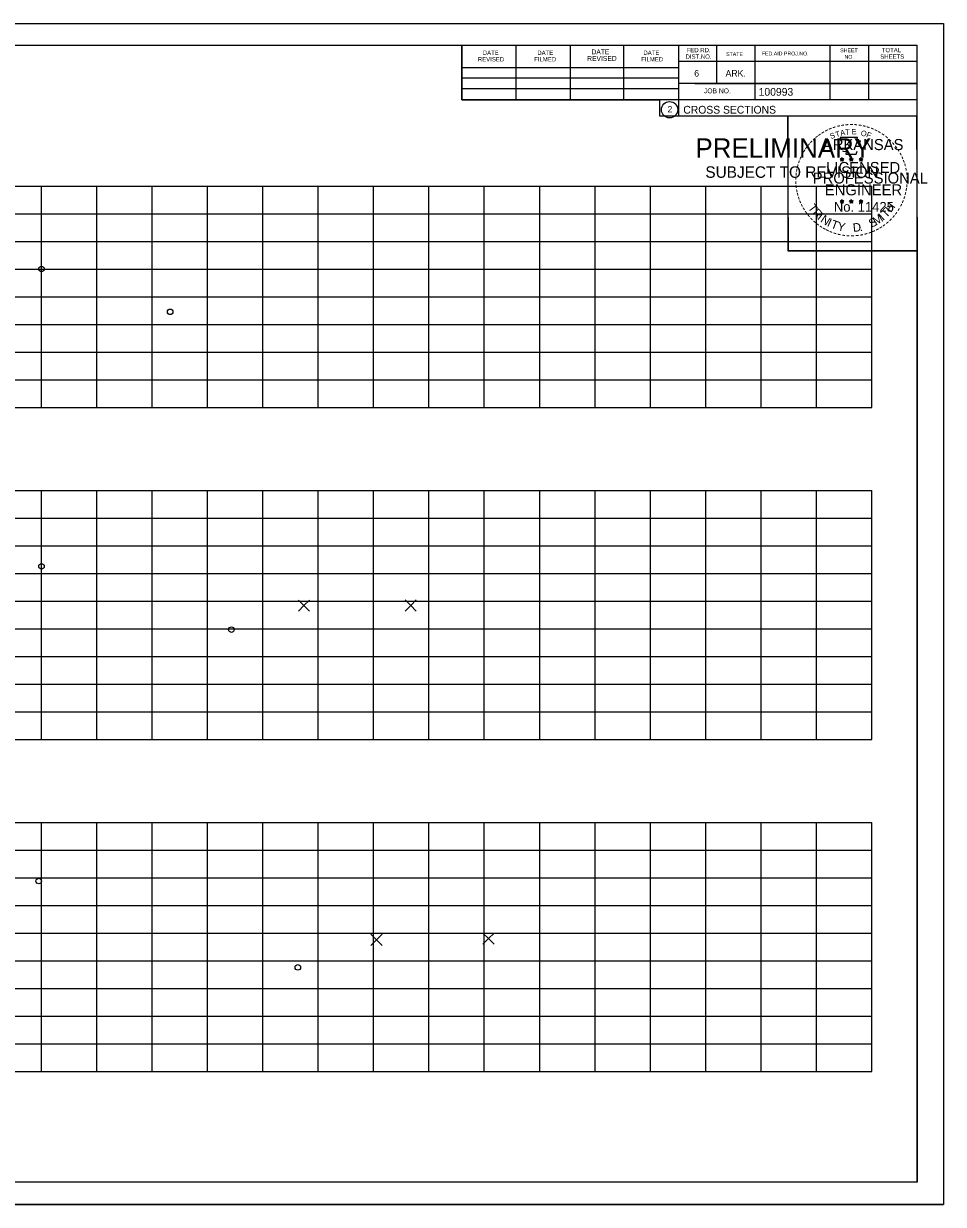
# Model space of a CAD drawing. Extents: x 4667 to 1632277, y -2100 to 724501.
# Drawn here: x 6136.3 to 6302.5, y -683.7 to -470.4 of the extents above; entities that cross this region are included whole.
import ezdxf

# ---------------------------------------------------------------- set-up
doc = ezdxf.new("R2010")
doc.units = 0
doc.layers.add('R_Grid', color=7, linetype='Continuous')
doc.layers.add('R_No Plot', color=7, linetype='Continuous')

msp = doc.modelspace()

# ---------------------------------------------------------------- linework, layer by layer
at = {"layer": 'R_Grid'}
for p, q in [((5989.52, -499.75), (6289.52, -499.75)), ((6139.52, -539.75), (6139.52, -499.75)), ((6149.52, -539.75), (6149.52, -499.75)), ((6159.52, -539.75), (6159.52, -499.75)), ((6169.52, -539.75), (6169.52, -499.75)), ((6179.52, -539.75), (6179.52, -499.75)), ((6189.52, -539.75), (6189.52, -499.75)), ((6199.52, -539.75), (6199.52, -499.75)), ((6209.52, -539.75), (6209.52, -499.75)), ((6219.52, -539.75), (6219.52, -499.75)), ((6229.52, -539.75), (6229.52, -499.75)), ((6239.52, -539.75), (6239.52, -499.75)), ((6249.52, -539.75), (6249.52, -499.75)), ((6259.52, -539.75), (6259.52, -499.75)), ((6269.52, -539.75), (6269.52, -499.75)), ((6279.52, -539.75), (6279.52, -499.75)), ((6289.52, -539.75), (6289.52, -499.75)), ((5989.52, -504.75), (6289.52, -504.75)), ((5989.52, -509.75), (6289.52, -509.75)), ((5989.52, -514.75), (6289.52, -514.75)), ((5989.52, -519.75), (6289.52, -519.75)), ((5989.52, -524.75), (6289.52, -524.75)), ((5989.52, -529.75), (6289.52, -529.75)), ((5989.52, -534.75), (6289.52, -534.75)), ((5989.52, -539.75), (6289.52, -539.75)), ((5989.52, -554.75), (6289.52, -554.75)), ((6139.52, -599.75), (6139.52, -554.75)), ((6149.52, -599.75), (6149.52, -554.75)), ((6159.52, -599.75), (6159.52, -554.75)), ((6169.52, -599.75), (6169.52, -554.75)), ((6179.52, -599.75), (6179.52, -554.75)), ((6189.52, -599.75), (6189.52, -554.75)), ((6199.52, -599.75), (6199.52, -554.75)), ((6209.52, -599.75), (6209.52, -554.75)), ((6219.52, -599.75), (6219.52, -554.75)), ((6229.52, -599.75), (6229.52, -554.75)), ((6239.52, -599.75), (6239.52, -554.75)), ((6249.52, -599.75), (6249.52, -554.75)), ((6259.52, -599.75), (6259.52, -554.75)), ((6269.52, -599.75), (6269.52, -554.75)), ((6279.52, -599.75), (6279.52, -554.75)), ((6289.52, -599.75), (6289.52, -554.75)), ((5989.52, -559.75), (6289.52, -559.75)), ((5989.52, -564.75), (6289.52, -564.75)), ((5989.52, -569.75), (6289.52, -569.75)), ((5989.52, -574.75), (6289.52, -574.75)), ((5989.52, -579.75), (6289.52, -579.75)), ((5989.52, -584.75), (6289.52, -584.75)), ((5989.52, -589.75), (6289.52, -589.75)), ((5989.52, -594.75), (6289.52, -594.75)), ((5989.52, -599.75), (6289.52, -599.75)), ((5989.52, -614.75), (6289.52, -614.75)), ((6139.52, -659.75), (6139.52, -614.75)), ((6149.52, -659.75), (6149.52, -614.75)), ((6159.52, -659.75), (6159.52, -614.75)), ((6169.52, -659.75), (6169.52, -614.75)), ((6179.52, -659.75), (6179.52, -614.75)), ((6189.52, -659.75), (6189.52, -614.75)), ((6199.52, -659.75), (6199.52, -614.75)), ((6209.52, -659.75), (6209.52, -614.75)), ((6219.52, -659.75), (6219.52, -614.75)), ((6229.52, -659.75), (6229.52, -614.75)), ((6239.52, -659.75), (6239.52, -614.75)), ((6249.52, -659.75), (6249.52, -614.75)), ((6259.52, -659.75), (6259.52, -614.75)), ((6269.52, -659.75), (6269.52, -614.75)), ((6279.52, -659.75), (6279.52, -614.75)), ((6289.52, -659.75), (6289.52, -614.75)), ((5989.52, -619.75), (6289.52, -619.75)), ((5989.52, -624.75), (6289.52, -624.75)), ((5989.52, -629.75), (6289.52, -629.75)), ((5989.52, -634.75), (6289.52, -634.75)), ((5989.52, -639.75), (6289.52, -639.75)), ((5989.52, -644.75), (6289.52, -644.75)), ((5989.52, -649.75), (6289.52, -649.75)), ((5989.52, -654.75), (6289.52, -654.75)), ((5989.52, -659.75), (6289.52, -659.75))]:
    msp.add_line(p, q, dxfattribs=at)
at = {"layer": 'R_No Plot'}
for p, q in [((5969.12, -470.4), (6302.46, -470.4)), ((5981.52, -474.29), (6297.7, -474.29)), ((6215.44, -484.17), (6215.44, -474.29)), ((6225.3, -484.17), (6225.3, -474.49)), ((6235.06, -484.17), (6235.06, -474.49)), ((6244.74, -484.17), (6244.74, -474.49)), ((6254.6, -474.29), (6254.6, -487.09)), ((6261.44, -474.29), (6261.44, -481.23)), ((6268.38, -474.29), (6268.38, -484.17)), ((6281.96, -474.29), (6281.96, -484.17)), ((6288.9, -474.29), (6288.9, -484.17)), ((6297.7, -679.75), (6297.7, -474.29)), ((6297.7, -477.23), (6254.6, -477.23)), ((6297.7, -477.21), (6297.7, -477.21)), ((6215.44, -478.31), (6254.6, -478.31)), ((6215.44, -480.17), (6254.6, -480.17)), ((6215.44, -484.17), (6215.44, -482.11)), ((6215.44, -482.11), (6254.6, -482.11)), ((6297.7, -481.23), (6254.6, -481.23)), ((6257.56, -481.23), (6297.7, -481.23)), ((6297.7, -484.17), (6215.44, -484.17)), ((6254.6, -487.09), (6297.7, -487.09)), ((6283.79, -494.84), (6284.14, -494.95)), ((6283.79, -494.84), (6284.04, -494.88)), ((6283.79, -494.84), (6284.03, -494.96)), ((6284.14, -494.59), (6284.1, -494.84)), ((6284.14, -494.95), (6284.14, -494.59)), ((6284.14, -494.59), (6284.19, -494.84)), ((6284.49, -494.84), (6284.14, -494.95)), ((6284.49, -494.84), (6284.2, -494.89)), ((6284.49, -494.84), (6284.28, -494.94)), ((6285.46, -494.84), (6285.81, -494.95)), ((6285.46, -494.84), (6285.71, -494.88)), ((6285.46, -494.84), (6285.7, -494.96)), ((6285.81, -494.59), (6285.77, -494.84)), ((6285.81, -494.95), (6285.81, -494.59)), ((6285.81, -494.59), (6285.86, -494.84)), ((6286.16, -494.84), (6285.81, -494.95)), ((6286.16, -494.84), (6285.87, -494.89)), ((6286.16, -494.84), (6285.95, -494.94)), ((6287.22, -494.85), (6287.57, -494.96)), ((6287.22, -494.85), (6287.48, -494.9)), ((6287.22, -494.85), (6287.46, -494.97)), ((6287.57, -494.6), (6287.53, -494.85)), ((6287.57, -494.96), (6287.57, -494.6)), ((6287.57, -494.6), (6287.62, -494.85)), ((6287.92, -494.85), (6287.57, -494.96)), ((6287.92, -494.85), (6287.63, -494.9)), ((6287.92, -494.85), (6287.72, -494.95)), ((6283.92, -495.25), (6284.14, -494.95)), ((6283.92, -495.25), (6284.05, -495)), ((6283.92, -495.25), (6284.14, -495.03)), ((6284.35, -495.25), (6284.14, -494.95)), ((6284.35, -495.25), (6284.14, -495.03)), ((6284.35, -495.25), (6284.21, -494.96)), ((6285.59, -495.25), (6285.81, -494.95)), ((6285.59, -495.25), (6285.72, -495)), ((6285.59, -495.25), (6285.81, -495.03)), ((6286.02, -495.25), (6285.81, -494.95)), ((6286.02, -495.25), (6285.81, -495.03)), ((6286.02, -495.25), (6285.88, -494.96)), ((6287.36, -495.26), (6287.57, -494.96)), ((6287.36, -495.26), (6287.48, -495.02)), ((6287.36, -495.26), (6287.57, -495.04)), ((6287.79, -495.26), (6287.57, -494.96)), ((6287.79, -495.26), (6287.57, -495.05)), ((6287.79, -495.26), (6287.65, -494.97)), ((6283.79, -502.41), (6284.13, -502.52)), ((6283.79, -502.41), (6284.04, -502.46)), ((6283.79, -502.41), (6284.02, -502.53)), ((6283.92, -502.82), (6284.13, -502.52)), ((6283.92, -502.82), (6284.04, -502.58)), ((6283.92, -502.82), (6284.13, -502.6)), ((6284.13, -502.16), (6284.09, -502.41)), ((6284.13, -502.52), (6284.13, -502.16)), ((6284.13, -502.16), (6284.18, -502.41)), ((6284.48, -502.41), (6284.13, -502.52)), ((6284.35, -502.82), (6284.13, -502.52)), ((6284.35, -502.82), (6284.13, -502.61)), ((6284.48, -502.41), (6284.2, -502.46)), ((6284.35, -502.82), (6284.21, -502.53)), ((6284.48, -502.41), (6284.28, -502.51)), ((6285.45, -502.41), (6285.8, -502.52)), ((6285.45, -502.41), (6285.71, -502.46)), ((6285.45, -502.41), (6285.69, -502.53)), ((6285.59, -502.82), (6285.8, -502.52)), ((6285.59, -502.82), (6285.71, -502.58)), ((6285.59, -502.82), (6285.8, -502.6)), ((6285.8, -502.16), (6285.76, -502.41)), ((6285.8, -502.52), (6285.8, -502.16)), ((6285.8, -502.16), (6285.85, -502.41)), ((6286.15, -502.41), (6285.8, -502.52)), ((6286.02, -502.82), (6285.8, -502.52)), ((6286.02, -502.82), (6285.8, -502.61)), ((6286.15, -502.41), (6285.86, -502.46)), ((6286.02, -502.82), (6285.88, -502.53)), ((6286.15, -502.41), (6285.95, -502.51)), ((6287.22, -502.42), (6287.57, -502.53)), ((6287.22, -502.42), (6287.47, -502.47)), ((6287.22, -502.42), (6287.46, -502.54)), ((6287.35, -502.83), (6287.57, -502.53)), ((6287.35, -502.83), (6287.48, -502.59)), ((6287.35, -502.83), (6287.57, -502.61)), ((6287.57, -502.17), (6287.53, -502.42)), ((6287.57, -502.53), (6287.57, -502.17)), ((6287.57, -502.17), (6287.62, -502.42)), ((6287.92, -502.42), (6287.57, -502.53)), ((6287.78, -502.83), (6287.57, -502.53)), ((6287.78, -502.83), (6287.57, -502.62)), ((6287.92, -502.42), (6287.63, -502.47)), ((6287.78, -502.83), (6287.65, -502.54)), ((6287.92, -502.42), (6287.71, -502.52)), ((6273.74, -509.55), (6273.74, -509.55)), ((6297.7, -679.75), (5981.52, -679.75)), ((5969.12, -683.73), (6302.46, -683.73))]:
    msp.add_line(p, q, dxfattribs=at)
for points in [[(5969.12, -470.4), (6302.46, -470.4), (6302.46, -683.74), (5969.12, -683.74)], [(6215.44, -474.29), (6215.44, -484.17), (6251.18, -484.17), (6251.18, -487.09), (6274.38, -487.09), (6274.38, -511.43), (6297.7, -511.43), (6297.7, -679.75), (5981.52, -679.75), (5981.52, -474.29)], [(6274.38, -487.09), (6297.58, -487.09), (6297.7, -511.43), (6274.5, -511.43)]]:
    msp.add_lwpolyline(points, close=True, dxfattribs=at)
for points in [[(6283.83, -490.96), (6284.1, -491.79)], [(6287.34, -491.88), (6287.48, -491.6), (6286.8, -491.62), (6286.95, -490.96), (6283.83, -490.96)], [(6284.14, -494.59), (6284.35, -495.25), (6283.79, -494.84), (6284.49, -494.84), (6283.92, -495.25), (6284.14, -494.59)], [(6284.32, -493.38), (6284.32, -493.47), (6284.89, -493.49), (6284.83, -493.96), (6286.7, -493.96), (6286.9, -493.43)], [(6285.81, -494.59), (6286.02, -495.25), (6285.46, -494.84), (6286.16, -494.84), (6285.59, -495.25), (6285.81, -494.59)], [(6287.57, -494.6), (6287.79, -495.26), (6287.22, -494.85), (6287.92, -494.85), (6287.36, -495.26), (6287.57, -494.6)], [(6284.13, -502.16), (6284.35, -502.82), (6283.79, -502.41), (6284.48, -502.41), (6283.92, -502.82), (6284.13, -502.16)], [(6285.8, -502.16), (6286.02, -502.82), (6285.45, -502.41), (6286.15, -502.41), (6285.59, -502.82), (6285.8, -502.16)], [(6287.57, -502.17), (6287.78, -502.83), (6287.22, -502.42), (6287.92, -502.42), (6287.35, -502.83), (6287.57, -502.17)], [(6186.93, -575.54), (6185.93, -574.54), (6186.93, -575.54), (6185.93, -576.54), (6186.93, -575.54), (6187.93, -576.54), (6186.93, -575.54), (6187.93, -574.54)], [(6206.23, -575.53), (6205.23, -574.53), (6206.23, -575.53), (6205.23, -576.53), (6206.23, -575.53), (6207.23, -576.53), (6206.23, -575.53), (6207.23, -574.53)], [(6200.04, -635.94), (6199.04, -634.94), (6200.04, -635.94), (6199.04, -636.94), (6200.04, -635.94), (6201.04, -636.94), (6200.04, -635.94), (6201.04, -634.94)], [(6220.28, -635.71), (6219.28, -634.71), (6220.28, -635.71), (6219.28, -636.71), (6220.28, -635.71), (6221.28, -636.71), (6220.28, -635.71), (6221.28, -634.71)]]:
    msp.add_lwpolyline(points, dxfattribs=at)
for centre, radius in [((6252.99, -485.96), 1.47), ((6284.14, -494.95), 0.172), ((6284.14, -494.95), 0.145), ((6284.14, -494.95), 0.116), ((6284.14, -494.95), 0.0991), ((6284.14, -494.95), 0.0747), ((6284.14, -494.95), 0.0495), ((6284.14, -494.95), 0.0296), ((6285.81, -494.95), 0.172), ((6285.81, -494.95), 0.145), ((6285.81, -494.95), 0.116), ((6285.81, -494.95), 0.0991), ((6285.81, -494.95), 0.0747), ((6285.81, -494.95), 0.0495), ((6285.81, -494.95), 0.0296), ((6287.57, -494.96), 0.172), ((6287.57, -494.96), 0.145), ((6287.57, -494.96), 0.116), ((6287.57, -494.96), 0.0991), ((6287.57, -494.96), 0.0747), ((6287.57, -494.96), 0.0495), ((6287.57, -494.96), 0.0296), ((6284.13, -502.52), 0.172), ((6284.13, -502.52), 0.145), ((6284.13, -502.52), 0.116), ((6284.13, -502.52), 0.0991), ((6284.13, -502.52), 0.0747), ((6284.13, -502.52), 0.0495), ((6284.13, -502.52), 0.0296), ((6285.8, -502.52), 0.172), ((6285.8, -502.52), 0.145), ((6285.8, -502.52), 0.116), ((6285.8, -502.52), 0.0991), ((6285.8, -502.52), 0.0747), ((6285.8, -502.52), 0.0495), ((6285.8, -502.52), 0.0296), ((6287.57, -502.53), 0.172), ((6287.57, -502.53), 0.145), ((6287.57, -502.53), 0.116), ((6287.57, -502.53), 0.0991), ((6287.57, -502.53), 0.0747), ((6287.57, -502.53), 0.0495), ((6287.57, -502.53), 0.0296), ((6139.52, -514.73), 0.5), ((6162.76, -522.48), 0.5), ((6139.52, -568.46), 0.5), ((6173.83, -579.89), 0.5), ((6139.02, -625.32), 0.5), ((6139.02, -625.32), 0.5), ((6185.82, -640.92), 0.5)]:
    msp.add_circle(centre, radius, dxfattribs=at)

# ---------------------------------------------------------------- texts
for s, height, rotation, p in [('DATE', 0.782, 360, (6219.24, -476.05)), ('DATE', 0.782, 360, (6229.1, -476.05)), ('DATE', 0.879, 360, (6238.88, -475.95)), ('DATE', 0.782, 360, (6248.26, -476.05)), ('FED.RD.', 0.782, 360, (6256.08, -475.57)), ('STATE', 0.684, 360, (6263.2, -476.25)), ('FED.AID PROJ.NO.', 0.684, 360, (6269.66, -476.15)), ('SHEET', 0.684, 360, (6283.82, -475.57)), ('TOTAL', 0.782, 360, (6291.34, -475.57)), ('REVISED', 0.782, 360, (6218.36, -477.23)), ('FILMED', 0.782, 360, (6228.52, -477.23)), ('REVISED', 0.879, 360, (6238.1, -477.13)), ('FILMED', 0.782, 360, (6247.86, -477.23)), ('DIST.NO.', 0.782, 360, (6255.88, -476.75)), ('NO.', 0.684, 360, (6284.6, -476.75)), ('SHEETS', 0.782, 360, (6291.06, -476.75)), ('6', 1.17, 360, (6257.44, -479.97)), ('ARK.', 1.172, 360, (6263.1, -479.97)), ('JOB NO.', 0.879, 360, (6259.2, -482.99)), ('100993', 1.4, 360, (6269.08, -483.43)), ('2', 1.17, 360, (6252.61, -486.45)), ('CROSS SECTIONS', 1.4, 360, (6255.47, -486.66)), ('-', 1.6, 0.1862, (6285.51, -489.25)), ('-', 1.6, 38.9507, (6279.66, -491.56)), ('-', 1.6, 36.2317, (6280.14, -491.19)), ('-', 1.6, 34.0636, (6280.71, -490.79)), ('-', 1.6, 28.7918, (6281.31, -490.42)), ('-', 1.6, 24.3072, (6281.94, -490.1)), ('S', 1, 21.594, (6282.18, -491.28)), ('-', 1.6, 19.1761, (6282.58, -489.83)), ('T', 1, 16.4036, (6283.1, -490.95)), ('-', 1.6, 13.6301, (6283.33, -489.59)), ('A', 1, 11.2132, (6283.92, -490.7)), ('-', 1.6, 10.2193, (6284.01, -489.43)), ('T', 1, 6.0228, (6284.77, -490.54)), ('-', 1.6, 5.8968, (6284.73, -489.32)), ('E', 1, 0.8323, (6285.88, -490.43)), ('-', 1.6, 357.743, (6286.23, -489.26)), ('-', 1.6, 352.1617, (6286.97, -489.32)), ('O', 1, 350.4515, (6287.48, -490.64)), ('-', 1.6, 347.2049, (6287.69, -489.43)), ('F', 1, 340.0707, (6288.44, -490.86)), ('-', 1.6, 342.3362, (6288.33, -489.59)), ('-', 1.6, 337.8551, (6289.06, -489.81)), ('-', 1.6, 334.1211, (6289.69, -490.08)), ('-', 1.6, 329.6409, (6290.27, -490.36)), ('-', 1.6, 325.8627, (6290.92, -490.73)), ('-', 1.6, 320.5297, (6291.53, -491.15)), ('PRELIMINARY', 3.5, 360, (6257.66, -494.63)), ('DWB', 0.01, 360, (6258.4, -492.78)), ('-', 1.6, 54.2325, (6277.96, -493.51)), ('-', 1.6, 50.6142, (6278.38, -492.94)), ('-', 1.6, 48.423, (6278.78, -492.46)), ('-', 1.6, 42.9622, (6279.23, -491.98)), ('ARKANSAS', 2, 360, (6280.68, -493.25)), ('-', 1.6, 315.5786, (6292.12, -491.64)), ('-', 1.6, 309.8797, (6292.69, -492.19)), ('-', 1.6, 306.6522, (6293.22, -492.79)), ('-', 1.6, 67.7743, (6277.07, -495.26)), ('-', 1.6, 62.8713, (6277.32, -494.65)), ('-', 1.6, 58.0706, (6277.64, -494.04)), ('-', 1.4, 303.6753, (6293.7, -493.36)), ('-', 1.6, 299.6684, (6294.02, -493.97)), ('-', 1.6, 294.6628, (6294.35, -494.58)), ('SUBJECT TO REVISION', 2.0751, 360, (6259.46, -498.26)), ('-', 1.6, 81.2013, (6276.52, -497.32)), ('-', 1.6, 75.461, (6276.65, -496.61)), ('-', 1.6, 72.3945, (6276.85, -495.89)), ('LICENSED', 2, 360, (6281.28, -497.4)), ('DWB', 0.01, 360, (6284.13, -494.96)), ('DWB', 0.01, 360, (6285.8, -494.96)), ('DWB', 0.01, 360, (6287.56, -494.97)), ('-', 1.6, 290.5728, (6294.6, -495.16)), ('-', 1.6, 285.1233, (6294.84, -495.74)), ('-', 1.6, 280.5493, (6295.04, -496.48)), ('-', 1.6, 94.1959, (6276.45, -499.44)), ('-', 1.6, 89.0622, (6276.42, -498.71)), ('-', 1.6, 85.1863, (6276.44, -498.01)), ('PROFESSIONAL', 2, 360, (6278.86, -499.3)), ('-', 1.6, 276.5962, (6295.2, -497.25)), ('-', 1.6, 274.3301, (6295.26, -497.97)), ('-', 1.6, 269.9407, (6295.29, -498.6)), ('-', 1.6, 98.9479, (6276.52, -500.1)), ('-', 1.6, 101.7149, (6276.66, -500.84)), ('-', 1.6, 105.4578, (6276.82, -501.43)), ('ENGINEER', 2, 360, (6281.04, -501.43)), ('-', 1.6, 255.7626, (6295.09, -500.6)), ('-', 1.6, 260.9953, (6295.2, -499.92)), ('-', 1.6, 263.5172, (6295.28, -499.27)), ('-', 1.6, 109.0874, (6277.04, -502.06)), ('-', 1.6, 114.0643, (6277.29, -502.66)), ('-', 1.6, 115.7289, (6277.59, -503.28)), ('T', 1.54, 306.0406, (6277.89, -503.69)), ('No. 11425', 1.757, 360, (6282.67, -504.38)), ('DWB', 0.01, 360, (6284.12, -502.53)), ('DWB', 0.01, 360, (6285.79, -502.53)), ('DWB', 0.01, 360, (6287.56, -502.54)), ('H', 1.54, 54.6088, (6293.01, -504.65)), ('-', 1.6, 244.6197, (6294.43, -502.62)), ('-', 1.6, 247.8887, (6294.69, -501.99)), ('-', 1.6, 252.8681, (6294.91, -501.32)), ('-', 1.6, 120.4471, (6277.95, -503.86)), ('-', 1.6, 125.8934, (6278.35, -504.42)), ('-', 1.6, 130.7181, (6278.82, -504.98)), ('-', 1.6, 134.2238, (6279.33, -505.52)), ('R', 1.54, 314.005, (6278.66, -504.73)), ('I', 1.54, 321.9694, (6279.56, -505.66)), ('N', 1.54, 326.5002, (6280.12, -506.14)), ('I', 1.54, 335.3603, (6281.33, -506.92)), ('S', 1.54, 26.9312, (6289.44, -507.32)), ('M', 1.54, 32.6563, (6290.28, -506.92)), ('I', 1.54, 42.1136, (6291.56, -506.07)), ('T', 1.54, 46.6444, (6292.12, -505.59)), ('-', 1.6, 225.7653, (6292.72, -505.15)), ('-', 1.6, 231.2538, (6293.2, -504.59)), ('-', 1.6, 233.8452, (6293.63, -504.02)), ('-', 1.6, 239.0712, (6294.03, -503.37)), ('-', 1.6, 138.9338, (6279.86, -505.99)), ('-', 1.6, 144.6463, (6280.41, -506.39)), ('-', 1.6, 148.0898, (6280.98, -506.76)), ('-', 1.6, 151.5704, (6281.55, -507.09)), ('-', 1.6, 154.6002, (6282.08, -507.33)), ('T', 1.54, 339.8912, (6281.99, -507.25)), ('Y', 1.54, 347.8556, (6283.21, -507.7)), ('D', 1.54, 6.3969, (6286.19, -508.05)), ('.', 1.54, 13.7642, (6287.39, -507.93)), ('-', 1.6, 204.2516, (6289.94, -507.19)), ('-', 1.6, 207.3568, (6290.56, -506.87)), ('-', 1.6, 212.2491, (6291.12, -506.52)), ('-', 1.6, 215.7363, (6291.65, -506.14)), ('-', 1.6, 221.0851, (6292.2, -505.66)), ('-', 1.6, 158.5612, (6282.7, -507.59)), ('-', 1.6, 162.7983, (6283.39, -507.8)), ('-', 1.6, 167.5555, (6284.1, -507.97)), ('-', 1.6, 173.1155, (6284.87, -508.08)), ('-', 1.6, 176.5183, (6285.62, -508.13)), ('-', 1.6, 181.5918, (6286.37, -508.11)), ('-', 1.6, 185.8167, (6287.18, -508.03)), ('-', 1.6, 191.2858, (6287.91, -507.9)), ('-', 1.6, 195.4743, (6288.64, -507.7)), ('-', 1.6, 200.7184, (6289.32, -507.46))]:
    msp.add_text(s, height=height, rotation=rotation, dxfattribs=at).set_placement(p)

doc.saveas('drawing.dxf')
